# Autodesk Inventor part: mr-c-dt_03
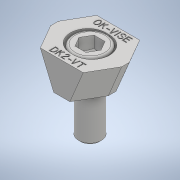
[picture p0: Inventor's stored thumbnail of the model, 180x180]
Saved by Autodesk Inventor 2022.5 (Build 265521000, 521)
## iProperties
Part Number: mr-c-dt_03
Material: 一般
Document SubType Name: Modeling
Designer: ImaoCorp
Density: 1 g/cm^3
Appearance: 既定
Author: ImaoCorp
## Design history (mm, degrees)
feature "mr-c-dt_03"
node "ソリッド1"
